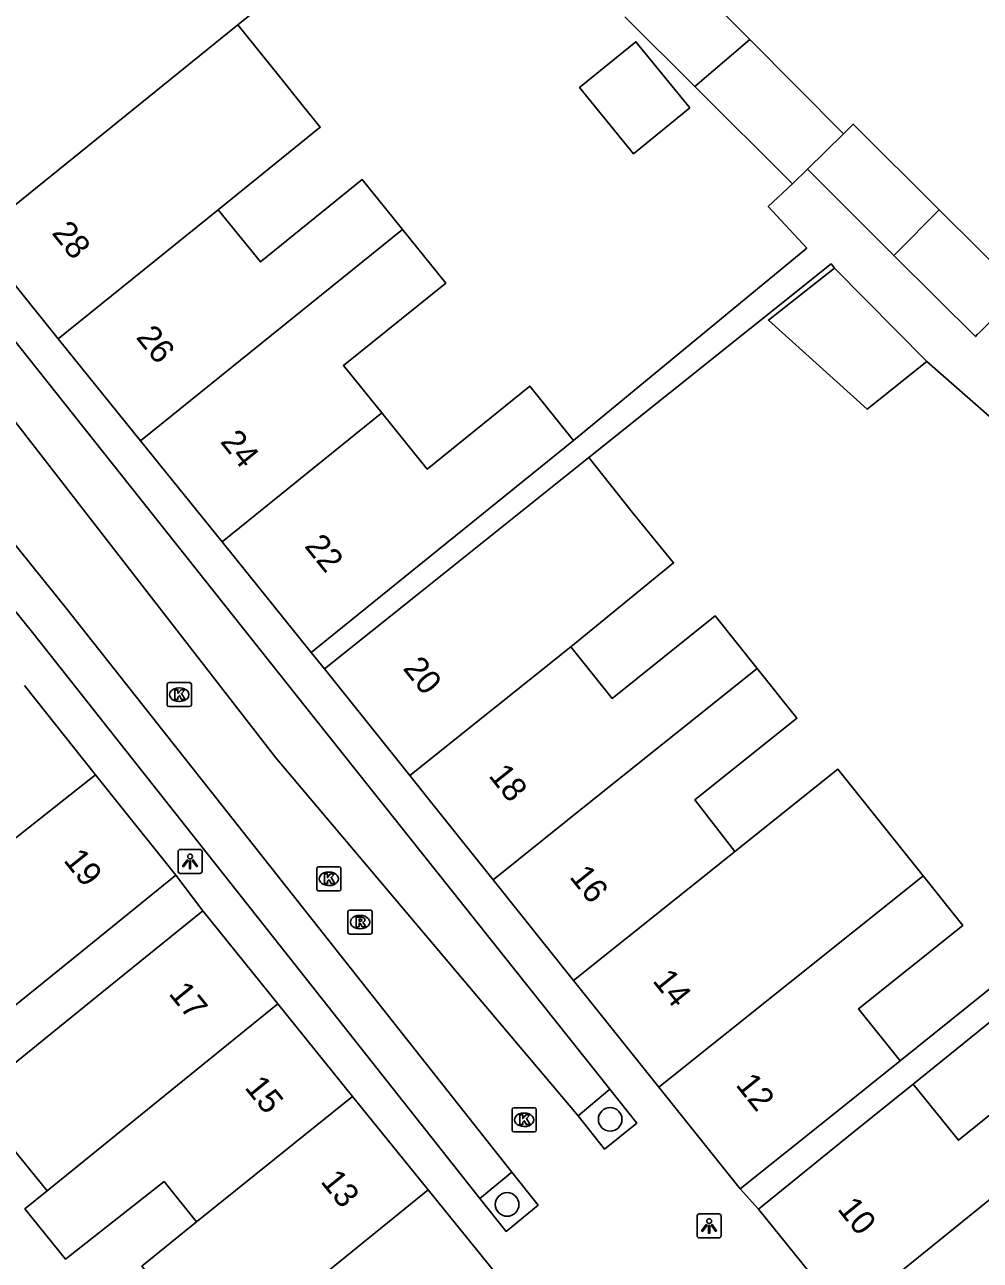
# Model space of a CAD drawing. Extents: x 161882 to 162509, y 381687 to 382379.
# Drawn here: x 162215.8 to 162255.4, y 381980.9 to 382032.1 of the extents above; entities that cross this region are included whole.
import ezdxf

# ---------------------------------------------------------------- set-up
doc = ezdxf.new("R2010")
doc.units = 0
for name, color, linetype in [('IMGEO_Boom', 7, 'Continuous'), ('IMGEO_Kolk', 7, 'Continuous'), ('IMGEO_Lichtpunt', 7, 'Continuous'), ('IMGEO_Pand', 7, 'Continuous'), ('IMGEO_Pand_nummerreeks', 7, 'Continuous'), ('IMGEO_Parkeervlak_open', 7, 'Continuous'), ('IMGEO_Rijbaan_lokaal_open', 7, 'Continuous'), ('IMGEO_Rioolput', 7, 'Continuous'), ('IMGEO_Voetpad_open', 7, 'Continuous')]:
    doc.layers.add(name, color=color, linetype=linetype)

msp = doc.modelspace()

# ---------------------------------------------------------------- linework, layer by layer
at = {"layer": 'IMGEO_Boom'}
for centre in [(162240.056, 381986.758), (162235.785, 381983.232)]:
    msp.add_circle(centre, 0.489, dxfattribs=at)
at = {"layer": 'IMGEO_Kolk'}
for p, q in [((162221.694, 382003.935), (162221.694, 382004.787)), ((162221.769, 382004.861), (162222.621, 382004.861)), ((162222.182, 382004.641), (162222.207, 382004.641)), ((162222.695, 382004.787), (162222.695, 382003.935)), ((162222.621, 382003.861), (162221.769, 382003.861)), ((162222.205, 382004.081), (162222.18, 382004.081)), ((162227.896, 381996.301), (162227.896, 381997.153)), ((162227.971, 381997.227), (162228.823, 381997.227)), ((162228.384, 381997.007), (162228.409, 381997.007)), ((162228.897, 381997.153), (162228.897, 381996.301)), ((162228.407, 381996.447), (162228.382, 381996.447)), ((162228.823, 381996.227), (162227.971, 381996.227)), ((162236.065, 381987.24), (162236.917, 381987.24)), ((162235.99, 381986.314), (162235.99, 381987.166)), ((162236.478, 381987.02), (162236.503, 381987.02)), ((162236.991, 381987.166), (162236.991, 381986.314)), ((162236.917, 381986.24), (162236.065, 381986.24)), ((162236.501, 381986.46), (162236.476, 381986.46))]:
    msp.add_line(p, q, dxfattribs=at)
for points in [[(162221.694, 382003.935), (162221.694, 382004.787)], [(162221.769, 382004.861), (162222.621, 382004.861)], [(162222.695, 382004.787), (162222.695, 382003.935)], [(162222.015, 382004.561), (162222.138, 382004.561), (162222.138, 382004.41), (162222.268, 382004.561), (162222.432, 382004.561), (162222.286, 382004.41), (162222.439, 382004.161), (162222.287, 382004.161), (162222.202, 382004.325), (162222.138, 382004.258), (162222.138, 382004.161), (162222.015, 382004.161), (162222.015, 382004.561)], [(162222.621, 382003.861), (162221.769, 382003.861)], [(162227.896, 381996.301), (162227.896, 381997.153)], [(162227.971, 381997.227), (162228.823, 381997.227)], [(162228.897, 381997.153), (162228.897, 381996.301)], [(162228.217, 381996.927), (162228.34, 381996.927), (162228.34, 381996.776), (162228.47, 381996.927), (162228.634, 381996.927), (162228.488, 381996.776), (162228.641, 381996.527), (162228.489, 381996.527), (162228.404, 381996.691), (162228.34, 381996.624), (162228.34, 381996.527), (162228.217, 381996.527), (162228.217, 381996.927)], [(162228.823, 381996.227), (162227.971, 381996.227)], [(162236.065, 381987.24), (162236.917, 381987.24)], [(162235.99, 381986.314), (162235.99, 381987.166)], [(162236.311, 381986.94), (162236.434, 381986.94), (162236.434, 381986.789), (162236.564, 381986.94), (162236.728, 381986.94), (162236.582, 381986.789), (162236.735, 381986.54), (162236.583, 381986.54), (162236.498, 381986.704), (162236.434, 381986.637), (162236.434, 381986.54), (162236.311, 381986.54), (162236.311, 381986.94)], [(162236.991, 381987.166), (162236.991, 381986.314)], [(162236.917, 381986.24), (162236.065, 381986.24)]]:
    msp.add_lwpolyline(points, dxfattribs=at)
for centre, start, end in [((162221.771, 382004.785), 91.552, 178.448), ((162221.771, 382004.785), 91.552, 178.448), ((162222.619, 382004.785), 1.552, 88.448), ((162222.619, 382004.785), 1.552, 88.448), ((162221.771, 382003.937), 181.552, 268.448), ((162221.771, 382003.937), 181.552, 268.448), ((162222.619, 382003.937), 271.552, 358.448), ((162222.619, 382003.937), 271.552, 358.448), ((162227.973, 381997.151), 91.552, 178.448), ((162227.973, 381997.151), 91.552, 178.448), ((162228.821, 381997.151), 1.552, 88.448), ((162228.821, 381997.151), 1.552, 88.448), ((162227.973, 381996.303), 181.552, 268.448), ((162227.973, 381996.303), 181.552, 268.448), ((162228.821, 381996.303), 271.552, 358.448), ((162228.821, 381996.303), 271.552, 358.448), ((162236.067, 381987.164), 91.552, 178.448), ((162236.067, 381987.164), 91.552, 178.448), ((162236.915, 381987.164), 1.552, 88.448), ((162236.915, 381987.164), 1.552, 88.448), ((162236.067, 381986.316), 181.552, 268.448), ((162236.067, 381986.316), 181.552, 268.448), ((162236.915, 381986.316), 271.552, 358.448), ((162236.915, 381986.316), 271.552, 358.448)]:
    msp.add_arc(centre, 0.0765, start, end, dxfattribs=at)
for centre, major_axis, ratio, start_param, end_param in [((162222.181, 382004.361), (-0.387, 0.002), 0.722429, 4.712389, 7.853982), ((162222.206, 382004.361), (-0.39, 0.002), 0.717154, 1.570796, 4.712389), ((162228.383, 381996.727), (-0.387, 0.002), 0.722429, 4.712389, 7.853982), ((162228.408, 381996.727), (-0.39, 0.002), 0.717154, 1.570796, 4.712389), ((162236.477, 381986.74), (-0.387, 0.002), 0.722429, 4.712389, 7.853982), ((162236.502, 381986.74), (-0.39, 0.002), 0.717154, 1.570796, 4.712389)]:
    msp.add_ellipse(centre, major_axis=major_axis, ratio=ratio, start_param=start_param, end_param=end_param, dxfattribs=at)
at = {"layer": 'IMGEO_Lichtpunt'}
for p, q in [((162222.144, 381997.853), (162222.144, 381997.046)), ((162222.144, 381997.853), (162222.144, 381997.046)), ((162223.046, 381997.948), (162222.238, 381997.948)), ((162223.046, 381997.948), (162222.238, 381997.948)), ((162223.14, 381997.046), (162223.14, 381997.853)), ((162223.14, 381997.046), (162223.14, 381997.853)), ((162222.238, 381996.952), (162223.046, 381996.952)), ((162222.238, 381996.952), (162223.046, 381996.952)), ((162243.66, 381982.744), (162243.66, 381981.937)), ((162243.66, 381982.744), (162243.66, 381981.937)), ((162244.562, 381982.839), (162243.754, 381982.839)), ((162244.562, 381982.839), (162243.754, 381982.839)), ((162244.656, 381981.937), (162244.656, 381982.744)), ((162244.656, 381981.937), (162244.656, 381982.744)), ((162243.754, 381981.843), (162244.562, 381981.843)), ((162243.754, 381981.843), (162244.562, 381981.843))]:
    msp.add_line(p, q, dxfattribs=at)
for points in [[(162222.518, 381997.517), (162222.557, 381997.489), (162222.369, 381997.227), (162222.331, 381997.254), (162222.518, 381997.517)], [(162222.62, 381997.469), (162222.667, 381997.469), (162222.667, 381997.147), (162222.62, 381997.147), (162222.62, 381997.469)], [(162222.73, 381997.489), (162222.768, 381997.516), (162222.955, 381997.254), (162222.916, 381997.226), (162222.73, 381997.489)], [(162244.034, 381982.408), (162244.073, 381982.38), (162243.885, 381982.118), (162243.847, 381982.145), (162244.034, 381982.408)], [(162244.136, 381982.36), (162244.183, 381982.36), (162244.183, 381982.038), (162244.136, 381982.038), (162244.136, 381982.36)], [(162244.246, 381982.38), (162244.284, 381982.407), (162244.471, 381982.145), (162244.432, 381982.117), (162244.246, 381982.38)]]:
    msp.add_lwpolyline(points, dxfattribs=at)
for centre in [(162222.643, 381997.651), (162244.159, 381982.542)]:
    msp.add_circle(centre, 0.0994, dxfattribs=at)
for centre, start, end in [((162222.238, 381997.853), 90, 180), ((162222.238, 381997.853), 90, 180), ((162223.046, 381997.853), 0, 90), ((162223.046, 381997.853), 0, 90), ((162222.238, 381997.046), 180, 270), ((162222.238, 381997.046), 180, 270), ((162223.046, 381997.046), 270, 0), ((162223.046, 381997.046), 270, 360), ((162243.754, 381982.744), 90, 180), ((162243.754, 381982.744), 90, 180), ((162244.562, 381982.744), 0, 90), ((162244.562, 381982.744), 0, 90), ((162243.754, 381981.937), 180, 270), ((162243.754, 381981.937), 180, 270), ((162244.562, 381981.937), 270, 0), ((162244.562, 381981.937), 270, 360)]:
    msp.add_arc(centre, 0.0946, start, end, dxfattribs=at)
at = {"layer": 'IMGEO_Pand'}
for points in [[(162229.19, 382035.797), (162224.622, 382032.11)], [(162245.842, 382031.505), (162242.804, 382034.555)], [(162243.563, 382029.562), (162240.668, 382032.445)], [(162213.756, 382023.338), (162224.622, 382032.11)], [(162224.622, 382032.11), (162226.346, 382029.969), (162227.28, 382028.809), (162228.037, 382027.868), (162223.809, 382024.455)], [(162243.357, 382028.674), (162241.121, 382031.414), (162238.791, 382029.512), (162241.027, 382026.773), (162243.357, 382028.674)], [(162243.563, 382029.562), (162245.842, 382031.505)], [(162249.729, 382027.601), (162245.842, 382031.505)], [(162247.62, 382025.524), (162243.563, 382029.562)], [(162253.7, 382024.45), (162250.136, 382028.001), (162249.729, 382027.601)], [(162249.729, 382027.601), (162248.235, 382026.13)], [(162248.235, 382026.13), (162247.62, 382025.524)], [(162251.819, 382022.562), (162248.235, 382026.13)], [(162223.809, 382024.455), (162225.557, 382022.29), (162229.781, 382025.7), (162231.446, 382023.637)], [(162217.176, 382019.101), (162223.809, 382024.455)], [(162251.819, 382022.562), (162251.897, 382022.64), (162253.7, 382024.45)], [(162253.7, 382024.45), (162257.075, 382021.088)], [(162231.446, 382023.637), (162220.589, 382014.873)], [(162231.446, 382023.637), (162233.239, 382021.416), (162229.002, 382017.996), (162230.587, 382016.033)], [(162217.176, 382019.101), (162213.756, 382023.338)], [(162257.075, 382021.088), (162255.389, 382019.396), (162255.272, 382019.278), (162255.194, 382019.2), (162253.646, 382020.741), (162251.819, 382022.562)], [(162249.36, 382022.034), (162246.614, 382019.879), (162250.707, 382016.184), (162253.178, 382018.163)], [(162249.36, 382022.034), (162253.178, 382018.163)], [(162220.589, 382014.873), (162217.176, 382019.101)], [(162230.587, 382016.033), (162232.466, 382013.705), (162236.726, 382017.145), (162238.542, 382014.896)], [(162230.587, 382016.033), (162223.967, 382010.689)], [(162223.967, 382010.689), (162220.589, 382014.873)], [(162238.542, 382014.896), (162231.553, 382009.253), (162227.662, 382006.112)], [(162228.214, 382005.429), (162232.125, 382008.556), (162239.168, 382014.186)], [(162239.168, 382014.186), (162240.974, 382011.926), (162242.688, 382009.819), (162238.423, 382006.339)], [(162227.662, 382006.112), (162223.967, 382010.689)], [(162246.154, 382005.442), (162244.411, 382007.622), (162240.135, 382004.204), (162239.206, 382005.367), (162238.423, 382006.339)], [(162238.423, 382006.339), (162231.749, 382001.007)], [(162231.749, 382001.007), (162228.214, 382005.429)], [(162246.154, 382005.442), (162239.344, 382000), (162235.201, 381996.689)], [(162245.228, 381997.86), (162243.572, 382000), (162247.801, 382003.382), (162246.154, 382005.442)], [(162215.779, 382004.732), (162218.725, 382001.041)], [(162208.068, 381992.613), (162217.408, 382000), (162218.725, 382001.041)], [(162218.725, 382001.041), (162219.556, 382000), (162222.052, 381996.872)], [(162253.031, 381996.847), (162251.207, 381999.129), (162249.497, 382001.269), (162245.228, 381997.86)], [(162235.201, 381996.689), (162232.554, 382000), (162231.749, 382001.007)], [(162238.54, 381992.513), (162245.055, 381997.719), (162245.228, 381997.86)], [(162222.052, 381996.872), (162218.164, 381993.729), (162215.349, 381991.453)], [(162238.54, 381992.513), (162235.201, 381996.689)], [(162253.031, 381996.847), (162252.937, 381996.769), (162242.076, 381988.089)], [(162252.081, 381989.179), (162250.354, 381991.339), (162254.674, 381994.792), (162253.031, 381996.847)], [(162213.594, 381987.654), (162216.723, 381990.185), (162219.278, 381992.251), (162223.166, 381995.394)], [(162223.166, 381995.394), (162226.281, 381991.541)], [(162242.076, 381988.089), (162238.54, 381992.513)], [(162226.281, 381991.541), (162216.713, 381983.795)], [(162226.281, 381991.541), (162229.38, 381987.708)], [(162252.612, 381988.219), (162254.492, 381985.892), (162258.729, 381989.315), (162260.442, 381987.195)], [(162245.446, 381983.874), (162249.352, 381986.997), (162252.081, 381989.179)], [(162245.446, 381983.874), (162242.076, 381988.089)], [(162252.612, 381988.219), (162250.091, 381986.182), (162246.202, 381983.039)], [(162216.713, 381983.795), (162215.108, 381985.78), (162214.602, 381986.407), (162213.594, 381987.654)], [(162222.913, 381982.51), (162229.38, 381987.708)], [(162229.38, 381987.708), (162232.515, 381983.832)], [(162249.797, 381978.591), (162260.442, 381987.195)], [(162222.913, 381982.51), (162221.564, 381984.179), (162217.48, 381980.971), (162215.796, 381983.053), (162216.713, 381983.795)], [(162232.515, 381983.832), (162222.035, 381975.349)], [(162232.515, 381983.832), (162235.753, 381979.827)], [(162249.797, 381978.591), (162246.202, 381983.039)], [(162222.035, 381975.349), (162220.386, 381977.389), (162222.143, 381978.81), (162220.639, 381980.671), (162222.913, 381982.51)]]:
    msp.add_lwpolyline(points, dxfattribs=at)
at = {"layer": 'IMGEO_Parkeervlak_open'}
for points in [[(162238.73, 381986.904), (162240.04, 381988.01)], [(162234.651, 381983.483), (162235.986, 381984.572)]]:
    msp.add_lwpolyline(points, dxfattribs=at)
at = {"layer": 'IMGEO_Rijbaan_lokaal_open'}
for points in [[(162205.956, 382027.701), (162197.948, 382037.505), (162199.568, 382038.828), (162201.169, 382036.868), (162214.404, 382020.232), (162227.861, 382003.318), (162240.04, 381988.01)], [(162234.651, 381983.483), (162216.168, 382006.86), (162203.528, 382022.543), (162197.21, 382030.314), (162198.527, 382031.389), (162203.307, 382025.537)], [(162238.73, 381986.904), (162226.199, 382001.747), (162207.512, 382025.796)], [(162204.863, 382023.632), (162217.503, 382007.949), (162235.986, 381984.572)], [(162227.662, 382006.112), (162228.214, 382005.429)], [(162222.052, 381996.872), (162223.166, 381995.394)], [(162240.04, 381988.01), (162241.161, 381986.601), (162239.822, 381985.527), (162238.73, 381986.904)], [(162235.986, 381984.572), (162237.066, 381983.206), (162235.745, 381982.117), (162234.651, 381983.483)], [(162246.202, 381983.039), (162245.446, 381983.874)]]:
    msp.add_lwpolyline(points, dxfattribs=at)
at = {"layer": 'IMGEO_Rioolput'}
for p, q in [((162229.263, 381995.433), (162230.115, 381995.433)), ((162229.188, 381994.507), (162229.188, 381995.359)), ((162229.676, 381995.213), (162229.701, 381995.213)), ((162230.189, 381995.359), (162230.189, 381994.507)), ((162230.115, 381994.433), (162229.263, 381994.433)), ((162229.699, 381994.653), (162229.674, 381994.653))]:
    msp.add_line(p, q, dxfattribs=at)
for points in [[(162229.263, 381995.433), (162230.115, 381995.433)], [(162229.188, 381994.507), (162229.188, 381995.359)], [(162229.777, 381995.131), (162229.525, 381995.133), (162229.525, 381994.733)], [(162229.525, 381994.733), (162229.649, 381994.733), (162229.649, 381994.895), (162229.66, 381994.895)], [(162229.703, 381995.052), (162229.649, 381995.052), (162229.649, 381994.971)], [(162229.649, 381994.971), (162229.701, 381994.971)], [(162230.189, 381995.359), (162230.189, 381994.507)], [(162230.115, 381994.433), (162229.263, 381994.433)], [(162229.707, 381994.866), (162229.778, 381994.733), (162229.918, 381994.733), (162229.853, 381994.859)]]:
    msp.add_lwpolyline(points, dxfattribs=at)
for centre, radius, start, end in [((162229.265, 381995.357), 0.0765, 91.552, 178.448), ((162229.265, 381995.357), 0.0765, 91.552, 178.448), ((162230.113, 381995.357), 0.0765, 1.552, 88.448), ((162230.113, 381995.357), 0.0765, 1.552, 88.448), ((162229.659, 381994.842), 0.0533, 26.0293, 88.6989), ((162229.685, 381995.16), 0.19, 274.7715, 282.9687), ((162229.709, 381994.956), 0.0964, 77.0061, 93.1865), ((162229.723, 381995.013), 0.0378, 276.6634, 79.6772), ((162229.776, 381995.021), 0.109, 350.3612, 89.416), ((162229.774, 381995.021), 0.112, 277.5842, 350.9817), ((162229.758, 381994.806), 0.108, 29.5134, 73.7905), ((162229.265, 381994.509), 0.0765, 181.552, 268.448), ((162229.265, 381994.509), 0.0765, 181.552, 268.448), ((162230.113, 381994.509), 0.0765, 271.552, 358.448), ((162230.113, 381994.509), 0.0765, 271.552, 358.448)]:
    msp.add_arc(centre, radius, start, end, dxfattribs=at)
for centre, major_axis, ratio, start_param, end_param in [((162229.675, 381994.933), (-0.387, 0.002), 0.722429, 4.712389, 7.853982), ((162229.7, 381994.933), (-0.39, 0.002), 0.717154, 1.570796, 4.712389)]:
    msp.add_ellipse(centre, major_axis=major_axis, ratio=ratio, start_param=start_param, end_param=end_param, dxfattribs=at)
at = {"layer": 'IMGEO_Voetpad_open'}
for points in [[(162238.542, 382014.896), (162248.207, 382022.866), (162246.609, 382024.581), (162247.62, 382025.524)], [(162239.168, 382014.186), (162249.214, 382022.217), (162249.36, 382022.034)], [(162253.178, 382018.163), (162257.785, 382014.128)], [(162267.246, 381999.596), (162267.033, 381999.872), (162252.612, 381988.219)], [(162262.585, 381997.63), (162252.081, 381989.179)]]:
    msp.add_lwpolyline(points, dxfattribs=at)

# ---------------------------------------------------------------- texts
at = {"layer": 'IMGEO_Pand_nummerreeks'}
for s, rotation, p in [('28', 308.9151, (162216.878, 382023.481)), ('26', 308.9143, (162220.371, 382019.156)), ('24', 308.9143, (162223.864, 382014.828)), ('22', 308.9143, (162227.356, 382010.503)), ('20', 308.6401, (162231.436, 382005.436)), ('18', 308.6401, (162234.986, 382000.994)), ('19', 308.5883, (162217.366, 381997.485)), ('16', 308.6404, (162238.339, 381996.799)), ('14', 308.6401, (162241.786, 381992.489)), ('17', 308.9552, (162221.726, 381991.959)), ('15', 308.9552, (162224.873, 381988.067)), ('12', 308.6404, (162245.23, 381988.179)), ('13', 308.9579, (162228.021, 381984.174)), ('10', 308.9404, (162249.444, 381983.036))]:
    msp.add_text(s, height=1, rotation=rotation, dxfattribs=at).set_placement(p)

doc.saveas('drawing.dxf')
